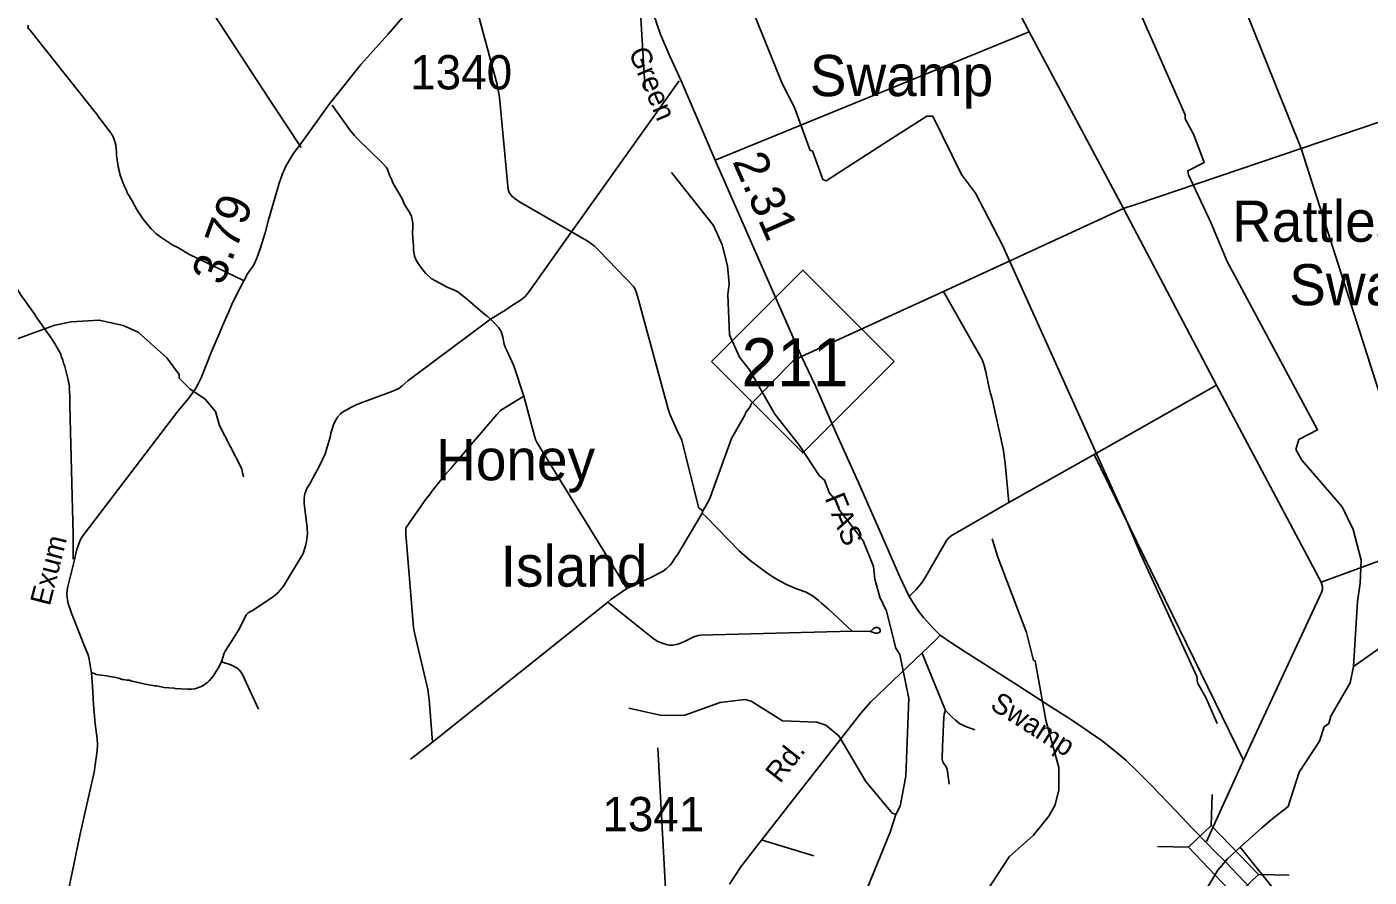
# Model space of a CAD drawing. Extents: x 2104537 to 2336408, y 34176 to 229611.
# Drawn here: x 2186795 to 2206373, y 142726 to 155125 of the extents above; entities that cross this region are included whole.
import ezdxf

# ---------------------------------------------------------------- set-up
doc = ezdxf.new("R2010")
doc.units = 0
for name, color, linetype in [('Exist Hydrographic Creek Single Shore', 7, 'Continuous'), ('Exist Hydrographic Misc Water Feature', 7, 'Continuous'), ('Exist Hydrographic Point Label', 7, 'Continuous'), ('Exist Hydrographic Swamp Label', 7, 'Continuous'), ('Exist Road Non-System Type 51', 7, 'Continuous'), ('Exist Road Primary NC Attributed', 7, 'Continuous'), ('Exist Road Primary NC Label', 7, 'Continuous'), ('Exist Road Primary NC Mileage Hundredths English Label', 7, 'Continuous'), ('Exist Road Primary NC Shield CELL', 7, 'Continuous'), ('Exist Road Primary NC Shield Number Label', 7, 'Continuous'), ('Exist Road Primary NC Structure Standard Bridge CELL', 7, 'Continuous'), ('Exist Road Secondary Mileage Hundredths English Label', 7, 'Continuous'), ('Exist Road Secondary Type 51 Attributed', 7, 'Continuous'), ('Exist Road Secondary Type 51 Label', 7, 'Continuous'), ('Exist Road Secondary Type 51 Number Label', 7, 'Continuous')]:
    doc.layers.add(name, color=color, linetype=linetype)

msp = doc.modelspace()

# ---------------------------------------------------------------- linework, layer by layer
at = {"layer": 'Exist Hydrographic Creek Single Shore'}
for points in [[(2200711, 142284), (2200744, 142375), (2200793, 142518), (2201122, 143021), (2201479, 143338), (2201701, 143616), (2201792, 143782), (2201849, 144000), (2201847, 144325), (2201658, 145015), (2201503, 145880), (2201478, 145887), (2201375, 146296), (2200959, 147393), (2200874, 147658)], [(2204493, 143163), (2204305, 142993), (2204166, 142828), (2203896, 142378), (2203518, 142370), (2202935, 142339), (2202610, 142355), (2202210, 142320), (2202011, 142275), (2201410, 142356), (2200886, 142251)]]:
    msp.add_lwpolyline(points, dxfattribs=at)
at = {"layer": 'Exist Hydrographic Misc Water Feature'}
for points in [[(2195813, 154205), (2195748, 155253), (2195697, 155428), (2195612, 155571), (2195159, 156016), (2194974, 156341), (2194922, 156582), (2194928, 156900), (2195080, 157933), (2195052, 158239), (2194943, 158415), (2194767, 158563), (2194138, 159110), (2193912, 159258)], [(2206144, 145797), (2206204, 146747), (2206243, 147012), (2206258, 147346), (2206138, 147795), (2205977, 148126), (2205390, 148807), (2205305, 148962), (2205346, 149106), (2205620, 149248), (2204303, 151705), (2204066, 152270), (2203736, 152969), (2203728, 153028), (2203968, 153145), (2203816, 153551), (2203689, 153783), (2203689, 153842), (2202825, 155805), (2202716, 156003), (2202605, 156301), (2202275, 157049)], [(2204158, 144966), (2203989, 145347), (2203871, 145562), (2203862, 145654), (2203041, 147432), (2202804, 147997), (2201019, 151949), (2200631, 152698), (2200429, 152971), (2200007, 153825), (2199923, 153824), (2199359, 153464), (2198455, 152881), (2198405, 152899), (2198252, 153315), (2198219, 153322), (2197990, 153947), (2197812, 154301), (2197278, 155624), (2197252, 155755), (2197134, 156007)], [(2196197, 153001), (2196810, 152228), (2196937, 151946), (2197014, 151640), (2197041, 151380), (2197017, 151223), (2197046, 150632), (2197190, 150308), (2197333, 150124), (2197704, 149477), (2198065, 149021), (2198351, 148582), (2198427, 148515), (2198503, 148324), (2198596, 148217), (2198638, 148091), (2198991, 147628), (2199144, 147255), (2199162, 147071), (2199238, 146807), (2199332, 146605), (2199468, 146064), (2199527, 145975), (2199657, 145332), (2199615, 144201), (2199534, 143760), (2199468, 143640)], [(2189172, 149846), (2189015, 150001), (2189015, 150056), (2188838, 150299), (2188420, 150672), (2188202, 150771), (2187852, 150850), (2187444, 150825), (2187203, 150774), (2186396, 150485), (2185973, 150266), (2185815, 150106), (2185739, 149915), (2185676, 149757), (2185540, 148631), (2185392, 148247)], [(2206144, 145797), (2207578, 146806), (2207611, 146798), (2207665, 146272), (2214529, 148836), (2219432, 150578)], [(2189954, 148565), (2189928, 148690), (2189607, 149313), (2189547, 149515), (2189396, 149695), (2189172, 149846)], [(2204493, 143163), (2204806, 143443), (2204944, 143561), (2205191, 143756), (2205354, 144257), (2205651, 144707), (2205716, 144916), (2205783, 144967), (2205815, 145075), (2206095, 145562), (2206144, 145797)], [(2199468, 143640), (2199418, 143657), (2199032, 144121), (2198636, 144785), (2198451, 144942), (2198318, 144984), (2197818, 145004), (2197358, 145292), (2197266, 145316), (2196908, 145274), (2196393, 145087), (2196059, 145084), (2195575, 145188)], [(2198610, 141301), (2198626, 141386), (2198709, 141512), (2198798, 141796), (2198814, 141979), (2199387, 143382), (2199468, 143640)], [(2205988, 137260), (2205689, 141669), (2204493, 143163)]]:
    msp.add_lwpolyline(points, dxfattribs=at)
at = {"layer": 'Exist Road Non-System Type 51'}
for p, q in [((2205381, 153350), (2203295, 158535)), ((2196835, 153182), (2201415, 155051)), ((2201415, 155051), (2202788, 152474)), ((2196311, 154340), (2194741, 152134)), ((2205381, 153350), (2207158, 153953)), ((2207220, 147598), (2205381, 153350)), ((2200165, 151268), (2202788, 152474)), ((2202788, 152474), (2204145, 149898)), ((2198094, 150318), (2200165, 151268)), ((2204145, 149898), (2202363, 148887)), ((2205675, 147027), (2204145, 149898)), ((2202363, 148887), (2201116, 148188)), ((2202363, 148887), (2204539, 144432)), ((2196646, 148033), (2196653, 148069)), ((2207220, 147598), (2205675, 147027)), ((2195267, 146736), (2192713, 144696)), ((2198832, 146311), (2199100, 146307)), ((2199851, 146003), (2200193, 145155)), ((2192713, 144696), (2192393, 144445)), ((2204539, 144432), (2203999, 143247)), ((2197507, 143271), (2198275, 143039))]:
    msp.add_line(p, q, dxfattribs=at)
for points in [[(2188790, 156387), (2188828, 156379), (2188840, 156371), (2188882, 156317), (2188892, 156295), (2189136, 155908), (2190388, 153984), (2190797, 153366)], [(2201415, 155051), (2200969, 155920), (2200958, 155950), (2200932, 156064)], [(2194741, 152134), (2193979, 152573), (2193917, 152616), (2193870, 152658), (2193858, 152669), (2193830, 152709), (2193819, 152737), (2193814, 152755), (2193688, 154096), (2193680, 154152), (2193661, 154245), (2193657, 154285), (2193365, 155365)], [(2189955, 151426), (2189160, 151809), (2188997, 151906), (2188923, 151942), (2188748, 152060), (2188678, 152113), (2188621, 152165), (2188611, 152179), (2188555, 152241), (2188493, 152320), (2188406, 152454), (2188360, 152531), (2188339, 152575), (2188311, 152617), (2188287, 152663), (2188275, 152679), (2188254, 152721), (2188254, 152727), (2188218, 152798), (2188189, 152868), (2188157, 152960), (2188157, 152974), (2188151, 152986), (2188139, 153040), (2188138, 153052), (2188128, 153084), (2188105, 153252), (2188105, 153292), (2188093, 153402), (2188074, 153469), (2188052, 153523), (2188050, 153533), (2188038, 153547), (2188024, 153573), (2188011, 153587), (2187901, 153742), (2187838, 153816), (2187824, 153836), (2187816, 153854), (2187788, 153884), (2186853, 155064), (2186821, 155100), (2186811, 155118), (2186821, 155150)], [(2184085, 154879), (2186661, 151294), (2186705, 151220), (2186880, 150981), (2186901, 150943), (2186919, 150923), (2186941, 150880), (2187147, 150593), (2187199, 150515), (2187290, 150352), (2187302, 150310), (2187322, 150266), (2187325, 150244), (2187337, 150206), (2187345, 150194), (2187400, 149977), (2187412, 149904), (2187417, 149863), (2187415, 149844), (2187419, 149821), (2187423, 149721), (2187424, 149605), (2187469, 147719), (2187473, 147363)], [(2193557, 150862), (2193509, 150908), (2193448, 150956), (2193198, 151169), (2193079, 151261), (2193022, 151288), (2192934, 151323), (2192694, 151455), (2192611, 151534), (2192553, 151604), (2192504, 151673), (2192473, 151725), (2192452, 151766), (2192448, 151782), (2192436, 151872), (2192435, 151948), (2192430, 151978), (2192420, 152120), (2192425, 152196), (2192423, 152262), (2192406, 152358), (2192377, 152425), (2192330, 152494), (2192301, 152546), (2192268, 152615), (2192140, 152843), (2192113, 152905), (2192084, 152962), (2192049, 153061), (2192034, 153081), (2191976, 153143), (2191613, 153496), (2191574, 153539), (2191517, 153609), (2191248, 153982)], [(2202788, 152474), (2202827, 152492), (2202970, 152536), (2205381, 153350)], [(2194741, 152134), (2194123, 151268), (2194087, 151220), (2194063, 151192), (2193991, 151136), (2193879, 151065), (2193768, 150990), (2193557, 150862)], [(2196653, 148069), (2196606, 148104), (2196590, 148121), (2196347, 149096), (2196334, 149132), (2196292, 149217), (2196174, 149477), (2196149, 149548), (2196126, 149645), (2195701, 151200), (2195680, 151263), (2195659, 151318), (2195645, 151337), (2195568, 151420), (2195527, 151459), (2195148, 151855), (2195068, 151933), (2195017, 151971), (2194967, 152004), (2194741, 152134)], [(2201116, 148188), (2201064, 148761), (2201037, 148973), (2200873, 149700), (2200851, 149777), (2200819, 149905), (2200780, 150097), (2200756, 150188), (2200733, 150260), (2200702, 150319), (2200595, 150502), (2200165, 151268)], [(2189636, 145868), (2189673, 145992), (2189688, 146022), (2189787, 146170), (2189881, 146330), (2189998, 146556), (2190021, 146580), (2190087, 146614), (2190373, 146804), (2190417, 146837), (2190458, 146873), (2190492, 146909), (2190538, 146969), (2190824, 147444), (2190859, 147556), (2190874, 147620), (2190890, 147732), (2190886, 147820), (2190867, 147940), (2190857, 148054), (2190845, 148136), (2190842, 148181), (2190840, 148237), (2190846, 148288), (2190852, 148318), (2190864, 148356), (2190875, 148384), (2190894, 148419), (2190923, 148462), (2191069, 148733), (2191147, 148899), (2191217, 149140), (2191228, 149196), (2191264, 149313), (2191287, 149367), (2191326, 149436), (2191369, 149484), (2191401, 149505), (2191520, 149575), (2191591, 149610), (2191673, 149643), (2192134, 149811), (2192189, 149835), (2192220, 149852), (2192269, 149889), (2192354, 149965), (2192409, 150007), (2193557, 150862)], [(2193557, 150862), (2193638, 150780), (2193679, 150734), (2193711, 150682), (2193737, 150602), (2193758, 150498), (2193777, 150446), (2193801, 150396), (2193896, 150183), (2194042, 149740)], [(2198094, 150318), (2197996, 150271), (2197960, 150247), (2197879, 150165), (2197433, 149700), (2197401, 149671), (2197362, 149627), (2197345, 149586), (2197288, 149509), (2197266, 149465), (2197074, 149124), (2196787, 148331), (2196758, 148247), (2196721, 148184), (2196694, 148130), (2196653, 148069)], [(2194042, 149740), (2193718, 149540), (2193699, 149524), (2193652, 149474), (2193048, 148766), (2192979, 148683), (2192889, 148583), (2192710, 148365), (2192663, 148295), (2192617, 148237), (2192330, 147824), (2192325, 147810), (2192322, 147759), (2192323, 147729), (2192433, 146366), (2192447, 146288), (2192631, 145525), (2192645, 145462), (2192663, 145317), (2192713, 144696)], [(2195547, 146933), (2194240, 149059), (2194215, 149109), (2194204, 149141), (2194042, 149740)], [(2196646, 148033), (2196288, 147437), (2196247, 147376), (2196217, 147328), (2196176, 147274), (2196121, 147222), (2196074, 147187), (2195885, 147090), (2195547, 146933)], [(2196646, 148033), (2196707, 147975), (2197185, 147486), (2197346, 147344), (2197435, 147274), (2197609, 147149), (2197689, 147097), (2197771, 147049), (2197886, 146987), (2198019, 146931), (2198160, 146880), (2198221, 146850), (2198263, 146823), (2198340, 146761), (2198383, 146719), (2198486, 146632), (2198620, 146513), (2198832, 146311)], [(2201116, 148188), (2200277, 147704), (2200242, 147674), (2200210, 147637), (2200187, 147603), (2199878, 147062), (2199846, 147013), (2199765, 146922), (2199658, 146812)], [(2204539, 144432), (2205676, 146879), (2205690, 146922), (2205692, 146959), (2205675, 147027)], [(2195267, 146736), (2195314, 146777), (2195547, 146933)], [(2195267, 146736), (2195925, 146211), (2195989, 146169), (2196060, 146137), (2196138, 146113), (2196166, 146109), (2196217, 146110), (2196240, 146113), (2196268, 146118), (2196318, 146134), (2196407, 146171), (2196523, 146229), (2196588, 146251), (2196616, 146255), (2198832, 146311)], [(2199100, 146307), (2199172, 146286), (2199204, 146285), (2199226, 146292), (2199234, 146300), (2199239, 146312), (2199240, 146329), (2199237, 146340), (2199226, 146356), (2199200, 146368), (2199180, 146367), (2199155, 146358), (2199134, 146343), (2199100, 146307)], [(2187732, 145713), (2187806, 145682), (2187878, 145670), (2187960, 145661), (2188004, 145651), (2188076, 145641), (2188154, 145622), (2188179, 145610), (2188212, 145608), (2188253, 145600), (2188294, 145597), (2188325, 145585), (2188397, 145571), (2188525, 145542), (2188657, 145516), (2188687, 145515), (2188797, 145493), (2188937, 145480), (2188973, 145474), (2189011, 145475), (2189039, 145471), (2189143, 145467), (2189196, 145468), (2189244, 145471), (2189326, 145499), (2189351, 145511), (2189434, 145571), (2189455, 145591), (2189512, 145658), (2189537, 145694), (2189588, 145772), (2189636, 145868)], [(2189636, 145868), (2189771, 145822), (2189818, 145800), (2189876, 145762), (2189892, 145748), (2189914, 145721), (2189944, 145673), (2189972, 145619), (2190176, 145177)], [(2200193, 145155), (2200175, 145105), (2200169, 145053), (2200150, 144628), (2200145, 144454), (2200149, 144419), (2200153, 144408), (2200164, 144389), (2200198, 144343), (2200209, 144323), (2200218, 144295), (2200224, 144269), (2200245, 144084)], [(2200193, 145155), (2200291, 145057), (2200338, 145015), (2200405, 144963), (2200435, 144945), (2200476, 144927), (2200620, 144876)], [(2196867, 142282), (2196794, 142337), (2196776, 142349), (2196747, 142360), (2196714, 142364), (2196692, 142361), (2196248, 142356), (2196182, 142364), (2196165, 142371), (2196138, 142386), (2196125, 142408), (2196116, 142470), (2196000, 144614)]]:
    msp.add_lwpolyline(points, dxfattribs=at)
at = {"layer": 'Exist Road Primary NC Attributed'}
for points in [[(2200117, 146257), (2200008, 146362), (2199872, 146510), (2199799, 146604), (2199728, 146715), (2199656, 146838), (2199528, 147107), (2199312, 147598), (2198919, 148493), (2198582, 149244), (2198291, 149902), (2198094, 150318), (2196835, 153182), (2196337, 154337), (2196175, 154697), (2196038, 155013), (2195982, 155168), (2195936, 155327), (2195868, 155669), (2195813, 156008), (2195584, 157480)], [(2204010, 143219), (2203792, 143440), (2203557, 143686), (2203202, 144057), (2202986, 144278), (2202822, 144430), (2202677, 144555), (2202479, 144715), (2202229, 144885), (2202031, 145022), (2201699, 145231), (2201246, 145525), (2200481, 146014), (2200259, 146158), (2200117, 146257)], [(2204271, 142953), (2204262, 142962), (2204133, 143092), (2204010, 143219)], [(2204645, 142562), (2204271, 142953)]]:
    msp.add_lwpolyline(points, dxfattribs=at)
at = {"layer": 'Exist Road Primary NC Shield CELL'}
msp.add_lwpolyline([(2196781, 150244), (2198113, 151576), (2199445, 150244), (2198113, 148912)], close=True, dxfattribs=at)
at = {"layer": 'Exist Road Primary NC Structure Standard Bridge CELL'}
for p, q in [((2204081, 143933), (2204071, 143481)), ((2203284, 143171), (2203736, 143161)), ((2204755, 142763), (2205208, 142753))]:
    msp.add_line(p, q, dxfattribs=at)
msp.add_lwpolyline([(2204071, 143481), (2204757, 142764), (2204422, 142444), (2203736, 143161)], close=True, dxfattribs=at)
at = {"layer": 'Exist Road Secondary Type 51 Attributed'}
for points in [[(2187402, 142541), (2187457, 142793), (2187569, 143334), (2187777, 144257), (2187804, 144430), (2187819, 144570), (2187827, 144661), (2187821, 144745), (2187794, 144961), (2187767, 145240), (2187754, 145509), (2187737, 145707), (2187721, 145814), (2187705, 145906), (2187688, 145970), (2187648, 146070), (2187552, 146302), (2187448, 146574), (2187396, 146718), (2187382, 146797), (2187377, 146862), (2187388, 146947), (2187484, 147332), (2187521, 147490), (2187552, 147588), (2187575, 147642), (2187602, 147690), (2187629, 147721), (2188982, 149501), (2189173, 149732), (2189261, 149856), (2189291, 149908), (2189337, 150006), (2189493, 150399), (2189591, 150624), (2189664, 150798), (2189732, 150950), (2189796, 151100), (2189906, 151320), (2190015, 151523), (2190102, 151647), (2190149, 151753), (2190205, 151904), (2190272, 152121), (2190321, 152313), (2190413, 152629), (2190474, 152846), (2190523, 152980), (2190574, 153093), (2190678, 153272), (2190801, 153435), (2191212, 154003), (2191671, 154582), (2192065, 155017), (2192309, 155299)], [(2200117, 146257), (2200064, 146196), (2199854, 145999), (2199104, 145284), (2198963, 145122), (2197423, 143152), (2197209, 142877), (2197043, 142622)]]:
    msp.add_lwpolyline(points, dxfattribs=at)

# ---------------------------------------------------------------- texts
at = {"layer": 'Exist Hydrographic Point Label'}
for s, p in [('Honey', (2192764, 148513)), ('Island', (2193707, 146962))]:
    msp.add_text(s, height=600, dxfattribs=at).set_placement(p)
at = {"layer": 'Exist Hydrographic Swamp Label'}
for s, p in [('Swamp', (2198215, 154115)), ('Rattlesnake', (2204373, 151991)), ('Swamp', (2205207, 151065))]:
    msp.add_text(s, height=600, dxfattribs=at).set_placement(p)
at = {"layer": 'Exist Road Primary NC Label'}
for s, rotation, p in [('Green', 292.7659, (2195567, 154757)), ('FAS', 292.1472, (2198429, 148253)), ('Swamp', 327.4689, (2200827, 145192))]:
    msp.add_text(s, height=300, rotation=rotation, dxfattribs=at).set_placement(p)
at = {"layer": 'Exist Road Primary NC Mileage Hundredths English Label'}
msp.add_text('2.31', height=500, rotation=293.7348, dxfattribs=at).set_placement((2197080, 153165))
at = {"layer": 'Exist Road Primary NC Shield Number Label'}
msp.add_text('211', height=700, dxfattribs=at).set_placement((2197218, 149885))
at = {"layer": 'Exist Road Secondary Mileage Hundredths English Label'}
msp.add_text('3.79', height=500, rotation=69.8391, dxfattribs=at).set_placement((2189654, 151338))
at = {"layer": 'Exist Road Secondary Type 51 Label'}
for s, rotation, p in [('Exum', 75.7907, (2187130, 146670)), ('Rd.', 51.8388, (2197780, 144082))]:
    msp.add_text(s, height=300, rotation=rotation, dxfattribs=at).set_placement(p)
at = {"layer": 'Exist Road Secondary Type 51 Number Label'}
for s, p in [('1340', (2192386, 154213)), ('1341', (2195189, 143396))]:
    msp.add_text(s, height=500, dxfattribs=at).set_placement(p)

doc.saveas('drawing.dxf')
